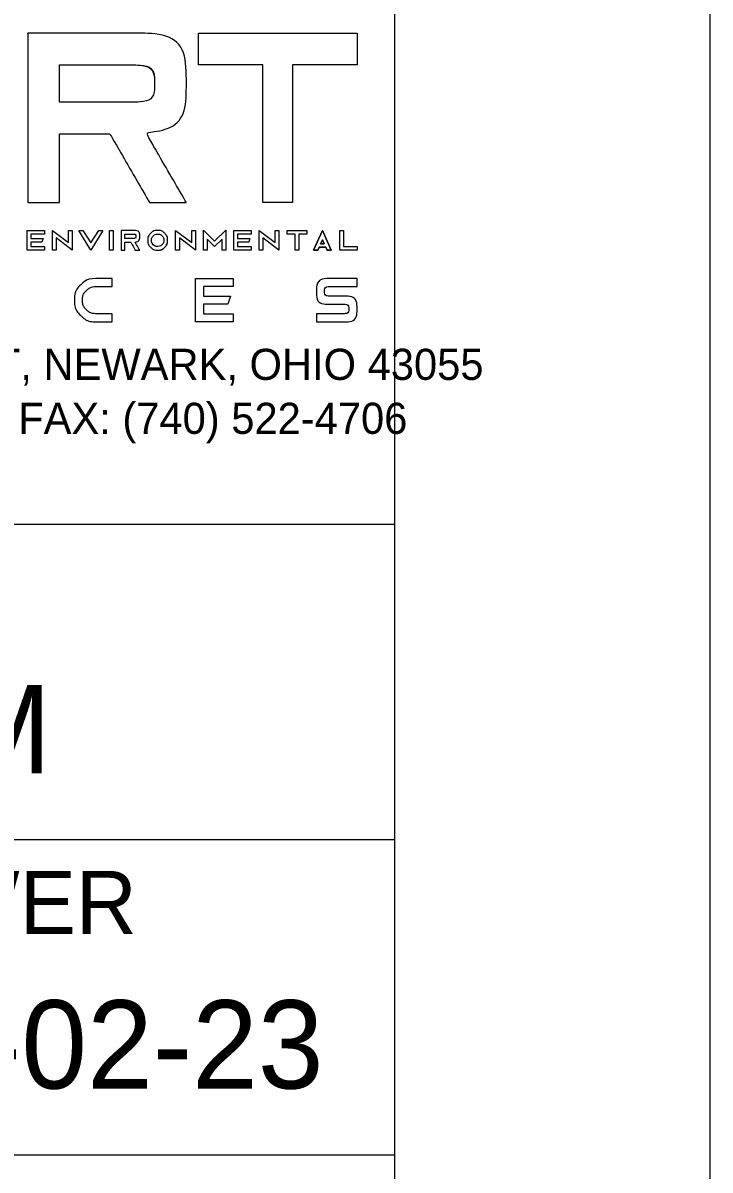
# Model space of a CAD drawing. Extents: x 0 to 34, y 0 to 22.
# Drawn here: x 32.911 to 34, y 1.976 to 3.795 of the extents above; entities that cross this region are included whole.
import ezdxf

# ---------------------------------------------------------------- set-up
doc = ezdxf.new("R2010")
doc.units = 0
for name, color, linetype in [('BORDER', 7, 'Continuous'), ('SH_Border', 7, 'Continuous'), ('SH_Cut_Line', 7, 'Continuous'), ('SH_Data', 7, 'Continuous')]:
    doc.layers.add(name, color=color, linetype=linetype)

msp = doc.modelspace()

# ---------------------------------------------------------------- linework, layer by layer
at = {"layer": 'BORDER'}
for p, q in [((33.1892, 3.7279), (33.1892, 3.7782)), ((33.1892, 3.7782), (33.4406, 3.7782)), ((33.4406, 3.7782), (33.4406, 3.7279)), ((33.2913, 3.7279), (33.1892, 3.7279)), ((33.2913, 3.51), (33.2913, 3.7279)), ((33.4406, 3.7279), (33.3384, 3.7279)), ((33.3384, 3.7279), (33.3384, 3.51)), ((33.3384, 3.51), (33.2913, 3.51)), ((32.9176, 3.4342), (32.9176, 3.4656)), ((32.9176, 3.4656), (32.9451, 3.4656)), ((32.9451, 3.4597), (32.9235, 3.4597)), ((32.9235, 3.4597), (32.9235, 3.4529)), ((32.9451, 3.4656), (32.9451, 3.4597)), ((32.9579, 3.4342), (32.9579, 3.4656)), ((32.9579, 3.4656), (32.9834, 3.4462)), ((32.9834, 3.4462), (32.9834, 3.4656)), ((32.9834, 3.4656), (32.9893, 3.4656)), ((32.9893, 3.4656), (32.9893, 3.4342)), ((33.0187, 3.4342), (32.9995, 3.4656)), ((32.9995, 3.4656), (33.0062, 3.4656)), ((33.0062, 3.4656), (33.0187, 3.446)), ((33.0187, 3.446), (33.0312, 3.4656)), ((33.0379, 3.4656), (33.0187, 3.4342)), ((33.0312, 3.4656), (33.0379, 3.4656)), ((33.0481, 3.4342), (33.0481, 3.4656)), ((33.0481, 3.4656), (33.054, 3.4656)), ((33.054, 3.4656), (33.054, 3.4342)), ((33.1531, 3.4342), (33.1531, 3.4656)), ((33.1531, 3.4656), (33.1786, 3.4462)), ((33.1786, 3.4462), (33.1786, 3.4656)), ((33.1786, 3.4656), (33.1845, 3.4656)), ((33.1845, 3.4656), (33.1845, 3.4342)), ((33.1973, 3.4342), (33.1973, 3.4661)), ((33.1973, 3.4661), (33.2149, 3.4484)), ((33.2149, 3.4484), (33.2326, 3.4661)), ((33.2326, 3.4661), (33.2326, 3.4342)), ((33.2453, 3.4342), (33.2453, 3.4656)), ((33.2453, 3.4656), (33.2728, 3.4656)), ((33.2728, 3.4597), (33.2512, 3.4597)), ((33.2512, 3.4597), (33.2512, 3.4529)), ((33.2728, 3.4656), (33.2728, 3.4597)), ((33.2856, 3.4342), (33.2856, 3.4656)), ((33.2856, 3.4656), (33.3111, 3.4462)), ((33.3111, 3.4462), (33.3111, 3.4656)), ((33.3111, 3.4656), (33.3169, 3.4656)), ((33.3169, 3.4656), (33.3169, 3.4342)), ((33.3297, 3.4597), (33.3297, 3.4656)), ((33.3297, 3.4656), (33.3611, 3.4656)), ((33.3425, 3.4597), (33.3297, 3.4597)), ((33.3425, 3.4342), (33.3425, 3.4597)), ((33.3611, 3.4597), (33.3483, 3.4597)), ((33.3483, 3.4597), (33.3483, 3.4342)), ((33.3611, 3.4656), (33.3611, 3.4597)), ((33.4131, 3.4656), (33.419, 3.4656)), ((33.4131, 3.4342), (33.4131, 3.4656)), ((33.419, 3.4656), (33.419, 3.4401)), ((32.9235, 3.4529), (32.9431, 3.4529)), ((32.9412, 3.447), (32.9235, 3.447)), ((32.9235, 3.447), (32.9235, 3.4401)), ((32.9235, 3.4401), (32.9451, 3.4401)), ((32.9431, 3.4529), (32.9412, 3.447)), ((32.9451, 3.4401), (32.9451, 3.4342)), ((32.9638, 3.4537), (32.9638, 3.4342)), ((32.9893, 3.4342), (32.9638, 3.4537)), ((33.159, 3.4537), (33.159, 3.4342)), ((33.1845, 3.4342), (33.159, 3.4537)), ((33.2031, 3.4519), (33.2031, 3.4342)), ((33.2149, 3.4401), (33.2031, 3.4519)), ((33.2267, 3.4519), (33.2149, 3.4401)), ((33.2267, 3.4342), (33.2267, 3.4519)), ((33.2512, 3.4529), (33.2708, 3.4529)), ((33.2689, 3.447), (33.2512, 3.447)), ((33.2512, 3.447), (33.2512, 3.4401)), ((33.2512, 3.4401), (33.2728, 3.4401)), ((33.2708, 3.4529), (33.2689, 3.447)), ((33.2728, 3.4401), (33.2728, 3.4342)), ((33.2914, 3.4537), (33.2914, 3.4342)), ((33.3169, 3.4342), (33.2914, 3.4537)), ((33.419, 3.4401), (33.4406, 3.4401)), ((33.4406, 3.4401), (33.4406, 3.4342)), ((32.9451, 3.4342), (32.9176, 3.4342)), ((32.9638, 3.4342), (32.9579, 3.4342)), ((33.054, 3.4342), (33.0481, 3.4342)), ((33.159, 3.4342), (33.1531, 3.4342)), ((33.2031, 3.4342), (33.1973, 3.4342)), ((33.2326, 3.4342), (33.2267, 3.4342)), ((33.2728, 3.4342), (33.2453, 3.4342)), ((33.2914, 3.4342), (33.2856, 3.4342)), ((33.3483, 3.4342), (33.3425, 3.4342)), ((33.4406, 3.4342), (33.4131, 3.4342)), ((33.1844, 3.3207), (33.1844, 3.3894)), ((33.1844, 3.3894), (33.2445, 3.3894)), ((33.2445, 3.3894), (33.2445, 3.3765)), ((33.2445, 3.3765), (33.1973, 3.3765)), ((33.1973, 3.3765), (33.1973, 3.3615)), ((33.1973, 3.3615), (33.2402, 3.3615)), ((33.2359, 3.3486), (33.1973, 3.3486)), ((33.1973, 3.3486), (33.1973, 3.3336)), ((33.2402, 3.3615), (33.2359, 3.3486)), ((33.1973, 3.3336), (33.2445, 3.3336)), ((33.2445, 3.3336), (33.2445, 3.3207)), ((33.2445, 3.3207), (33.1844, 3.3207))]:
    msp.add_line(p, q, dxfattribs=at)
for points in [[(33.2913, 3.7279), (33.1892, 3.7279), (33.1892, 3.7782), (33.4406, 3.7782), (33.4406, 3.7279), (33.3384, 3.7279), (33.3384, 3.51), (33.2913, 3.51), (33.2913, 3.7279)], [(32.9235, 3.4401), (32.9451, 3.4401), (32.9451, 3.4342), (32.9176, 3.4342), (32.9176, 3.4656), (32.9451, 3.4656), (32.9451, 3.4597), (32.9235, 3.4597), (32.9235, 3.4529), (32.9431, 3.4529), (32.9412, 3.447), (32.9235, 3.447), (32.9235, 3.4401)], [(32.9638, 3.4537), (32.9638, 3.4342), (32.9579, 3.4342), (32.9579, 3.4656), (32.9834, 3.4462), (32.9834, 3.4656), (32.9893, 3.4656), (32.9893, 3.4342), (32.9638, 3.4537)], [(33.0062, 3.4656), (33.0187, 3.446), (33.0312, 3.4656), (33.0379, 3.4656), (33.0187, 3.4342), (32.9995, 3.4656), (33.0062, 3.4656)], [(33.054, 3.4342), (33.0481, 3.4342), (33.0481, 3.4656), (33.054, 3.4656), (33.054, 3.4342)], [(33.159, 3.4537), (33.159, 3.4342), (33.1531, 3.4342), (33.1531, 3.4656), (33.1786, 3.4462), (33.1786, 3.4656), (33.1845, 3.4656), (33.1845, 3.4342), (33.159, 3.4537)], [(33.2031, 3.4519), (33.2031, 3.4342), (33.1973, 3.4342), (33.1973, 3.4661), (33.2149, 3.4484), (33.2326, 3.4661), (33.2326, 3.4342), (33.2267, 3.4342), (33.2267, 3.4519), (33.2149, 3.4401), (33.2031, 3.4519)], [(33.2512, 3.4401), (33.2728, 3.4401), (33.2728, 3.4342), (33.2453, 3.4342), (33.2453, 3.4656), (33.2728, 3.4656), (33.2728, 3.4597), (33.2512, 3.4597), (33.2512, 3.4529), (33.2708, 3.4529), (33.2689, 3.447), (33.2512, 3.447), (33.2512, 3.4401)], [(33.2914, 3.4537), (33.2914, 3.4342), (33.2856, 3.4342), (33.2856, 3.4656), (33.3111, 3.4462), (33.3111, 3.4656), (33.3169, 3.4656), (33.3169, 3.4342), (33.2914, 3.4537)], [(33.3425, 3.4597), (33.3297, 3.4597), (33.3297, 3.4656), (33.3611, 3.4656), (33.3611, 3.4597), (33.3483, 3.4597), (33.3483, 3.4342), (33.3425, 3.4342), (33.3425, 3.4597)], [(33.3856, 3.4656), (33.3997, 3.4342), (33.393, 3.4342), (33.3909, 3.4389), (33.3804, 3.4389), (33.3783, 3.4342), (33.3716, 3.4342), (33.3856, 3.4656)], [(33.4131, 3.4656), (33.419, 3.4656), (33.419, 3.4401), (33.4406, 3.4401), (33.4406, 3.4342), (33.4131, 3.4342), (33.4131, 3.4656)], [(33.3884, 3.4444), (33.3856, 3.4509), (33.3828, 3.4444), (33.3884, 3.4444)], [(33.1973, 3.3336), (33.2445, 3.3336), (33.2445, 3.3207), (33.1844, 3.3207), (33.1844, 3.3894), (33.2445, 3.3894), (33.2445, 3.3765), (33.1973, 3.3765), (33.1973, 3.3615), (33.2402, 3.3615), (33.2359, 3.3486), (33.1973, 3.3486), (33.1973, 3.3336)]]:
    msp.add_lwpolyline(points, dxfattribs=at)
for points in [[(33.3716, 3.4342), (33.3783, 3.4342), (33.3804, 3.4389), (33.3909, 3.4389), (33.393, 3.4342), (33.3997, 3.4342), (33.3856, 3.4656)], [(33.3828, 3.4444), (33.3856, 3.4509), (33.3884, 3.4444)]]:
    msp.add_lwpolyline(points, close=True, dxfattribs=at)
for points, degree in [([(32.9187, 3.7782), (32.9187, 3.7782), (32.9187, 3.51), (32.9187, 3.51)], 2), ([(32.9187, 3.51), (32.9187, 3.51), (32.969, 3.51), (32.969, 3.51), (32.969, 3.51), (32.969, 3.6189), (32.969, 3.6189), (32.969, 3.6189), (33.0488, 3.6189), (33.0488, 3.6189), (33.0488, 3.6189), (33.1116, 3.51), (33.1116, 3.51), (33.1116, 3.51), (33.1698, 3.51), (33.1698, 3.51), (33.1698, 3.51), (33.1061, 3.6203), (33.1061, 3.6203), (33.1488, 3.6261), (33.1701, 3.6522), (33.1701, 3.6986), (33.1701, 3.7516), (33.1422, 3.7782), (33.0863, 3.7782), (33.0863, 3.7782), (32.9187, 3.7782), (32.9187, 3.7782)], 3), ([(32.9187, 3.7782), (32.9187, 3.7782), (33.0863, 3.7782), (33.0863, 3.7782), (33.1422, 3.7782), (33.1701, 3.7516), (33.1701, 3.6986), (33.1701, 3.6522), (33.1488, 3.6261), (33.1061, 3.6203), (33.1061, 3.6203), (33.1698, 3.51), (33.1698, 3.51), (33.1698, 3.51), (33.1116, 3.51), (33.1116, 3.51), (33.1116, 3.51), (33.0488, 3.6189), (33.0488, 3.6189), (33.0488, 3.6189), (32.969, 3.6189), (32.969, 3.6189), (32.969, 3.6189), (32.969, 3.51), (32.969, 3.51), (32.969, 3.51), (32.9187, 3.51), (32.9187, 3.51), (32.9187, 3.51), (32.9187, 3.7782), (32.9187, 3.7782)], 3), ([(32.969, 3.7279), (32.969, 3.7279), (33.0863, 3.7279), (33.0863, 3.7279)], 2), ([(33.0863, 3.7279), (33.1086, 3.7279), (33.1198, 3.7181), (33.1198, 3.6986), (33.1198, 3.679), (33.1086, 3.6692), (33.0863, 3.6692), (33.0863, 3.6692), (32.969, 3.6692), (32.969, 3.6692), (32.969, 3.6692), (32.969, 3.7279), (32.969, 3.7279)], 3), ([(32.969, 3.7279), (32.969, 3.7279), (32.969, 3.6692), (32.969, 3.6692), (32.969, 3.6692), (33.0863, 3.6692), (33.0863, 3.6692), (33.1086, 3.6692), (33.1198, 3.679), (33.1198, 3.6986), (33.1198, 3.7181), (33.1086, 3.7279), (33.0863, 3.7279), (33.0863, 3.7279), (32.969, 3.7279), (32.969, 3.7279)], 3), ([(33.0668, 3.4656), (33.0668, 3.4656), (33.0668, 3.4342), (33.0668, 3.4342)], 2), ([(33.0668, 3.4656), (33.0668, 3.4656), (33.0864, 3.4656), (33.0864, 3.4656), (33.0929, 3.4656), (33.0962, 3.4625), (33.0962, 3.4563), (33.0962, 3.4509), (33.0937, 3.4478), (33.0887, 3.4471), (33.0887, 3.4471), (33.0962, 3.4342), (33.0962, 3.4342), (33.0962, 3.4342), (33.0894, 3.4342), (33.0894, 3.4342), (33.0894, 3.4342), (33.082, 3.447), (33.082, 3.447), (33.082, 3.447), (33.0727, 3.447), (33.0727, 3.447), (33.0727, 3.447), (33.0727, 3.4342), (33.0727, 3.4342), (33.0727, 3.4342), (33.0668, 3.4342), (33.0668, 3.4342), (33.0668, 3.4342), (33.0668, 3.4656), (33.0668, 3.4656)], 3), ([(33.0668, 3.4342), (33.0668, 3.4342), (33.0727, 3.4342), (33.0727, 3.4342), (33.0727, 3.4342), (33.0727, 3.447), (33.0727, 3.447), (33.0727, 3.447), (33.082, 3.447), (33.082, 3.447), (33.082, 3.447), (33.0894, 3.4342), (33.0894, 3.4342), (33.0894, 3.4342), (33.0962, 3.4342), (33.0962, 3.4342), (33.0962, 3.4342), (33.0887, 3.4471), (33.0887, 3.4471), (33.0937, 3.4478), (33.0962, 3.4509), (33.0962, 3.4563), (33.0962, 3.4625), (33.0929, 3.4656), (33.0864, 3.4656), (33.0864, 3.4656), (33.0668, 3.4656), (33.0668, 3.4656)], 3), ([(33.0727, 3.4597), (33.0727, 3.4597), (33.0864, 3.4597), (33.0864, 3.4597)], 2), ([(33.0727, 3.4597), (33.0727, 3.4597), (33.0727, 3.4529), (33.0727, 3.4529), (33.0727, 3.4529), (33.0864, 3.4529), (33.0864, 3.4529), (33.089, 3.4529), (33.0903, 3.454), (33.0903, 3.4563), (33.0903, 3.4586), (33.089, 3.4597), (33.0864, 3.4597), (33.0864, 3.4597), (33.0727, 3.4597), (33.0727, 3.4597)], 3), ([(33.0864, 3.4597), (33.089, 3.4597), (33.0903, 3.4586), (33.0903, 3.4563), (33.0903, 3.454), (33.089, 3.4529), (33.0864, 3.4529), (33.0864, 3.4529), (33.0727, 3.4529), (33.0727, 3.4529), (33.0727, 3.4529), (33.0727, 3.4597), (33.0727, 3.4597)], 3), ([(33.1247, 3.4342), (33.1203, 3.4342), (33.1166, 3.4358), (33.1136, 3.4388), (33.1105, 3.4419), (33.109, 3.4456), (33.109, 3.4499), (33.109, 3.4543), (33.1105, 3.4579), (33.1136, 3.461), (33.1166, 3.4641), (33.1203, 3.4656), (33.1247, 3.4656), (33.129, 3.4656), (33.1327, 3.4641), (33.1358, 3.461), (33.1388, 3.4579), (33.1404, 3.4543), (33.1404, 3.4499), (33.1404, 3.4456), (33.1388, 3.4419), (33.1358, 3.4388), (33.1327, 3.4358), (33.129, 3.4342), (33.1247, 3.4342)], 3), ([(33.1358, 3.4388), (33.1388, 3.4419), (33.1404, 3.4456), (33.1404, 3.4499), (33.1404, 3.4543), (33.1388, 3.4579), (33.1358, 3.461), (33.1327, 3.4641), (33.129, 3.4656), (33.1247, 3.4656), (33.1203, 3.4656), (33.1166, 3.4641), (33.1136, 3.461), (33.1105, 3.4579), (33.109, 3.4543), (33.109, 3.4499), (33.109, 3.4456), (33.1105, 3.4419), (33.1136, 3.4388), (33.1166, 3.4358), (33.1203, 3.4342), (33.1247, 3.4342)], 3), ([(33.1247, 3.4401), (33.1274, 3.4401), (33.1297, 3.4411), (33.1316, 3.443), (33.1335, 3.4449), (33.1345, 3.4472), (33.1345, 3.4499), (33.1345, 3.4526), (33.1335, 3.4549), (33.1316, 3.4569), (33.1297, 3.4588), (33.1274, 3.4597), (33.1247, 3.4597), (33.122, 3.4597), (33.1196, 3.4588), (33.1177, 3.4569), (33.1158, 3.4549), (33.1149, 3.4526), (33.1149, 3.4499), (33.1149, 3.4472), (33.1158, 3.4449), (33.1177, 3.443), (33.1196, 3.4411), (33.122, 3.4401), (33.1247, 3.4401)], 3), ([(33.1177, 3.443), (33.1158, 3.4449), (33.1149, 3.4472), (33.1149, 3.4499), (33.1149, 3.4526), (33.1158, 3.4549), (33.1177, 3.4569), (33.1196, 3.4588), (33.122, 3.4597), (33.1247, 3.4597), (33.1274, 3.4597), (33.1297, 3.4588), (33.1316, 3.4569), (33.1335, 3.4549), (33.1345, 3.4526), (33.1345, 3.4499), (33.1345, 3.4472), (33.1335, 3.4449), (33.1316, 3.443), (33.1297, 3.4411), (33.1274, 3.4401), (33.1247, 3.4401)], 3), ([(33.1247, 3.4401), (33.122, 3.4401), (33.1196, 3.4411), (33.1177, 3.443)], 2), ([(33.1247, 3.4342), (33.129, 3.4342), (33.1327, 3.4358), (33.1358, 3.4388)], 2), ([(33.0269, 3.3894), (33.0269, 3.3894), (33.0527, 3.3894), (33.0527, 3.3894), (33.0527, 3.3894), (33.0527, 3.3765), (33.0527, 3.3765), (33.0527, 3.3765), (33.0269, 3.3765), (33.0269, 3.3765), (33.021, 3.3765), (33.0159, 3.3744), (33.0118, 3.3702), (33.0076, 3.366), (33.0055, 3.361), (33.0055, 3.3551), (33.0055, 3.3491), (33.0076, 3.3441), (33.0118, 3.3399), (33.0159, 3.3357), (33.021, 3.3336), (33.0269, 3.3336), (33.0269, 3.3336), (33.0527, 3.3336), (33.0527, 3.3336), (33.0527, 3.3336), (33.0527, 3.3207), (33.0527, 3.3207), (33.0527, 3.3207), (33.0269, 3.3207), (33.0269, 3.3207), (33.0175, 3.3207), (33.0094, 3.3241), (33.0027, 3.3308), (32.9959, 3.3375), (32.9926, 3.3456), (32.9926, 3.3551), (32.9926, 3.3645), (32.9959, 3.3726), (33.0027, 3.3793), (33.0094, 3.3861), (33.0175, 3.3894), (33.0269, 3.3894)], 3), ([(33.0269, 3.3894), (33.0269, 3.3894), (33.0527, 3.3894), (33.0527, 3.3894), (33.0527, 3.3894), (33.0527, 3.3765), (33.0527, 3.3765), (33.0527, 3.3765), (33.0269, 3.3765), (33.0269, 3.3765), (33.021, 3.3765), (33.0159, 3.3744), (33.0118, 3.3702), (33.0076, 3.366), (33.0055, 3.361), (33.0055, 3.3551), (33.0055, 3.3491), (33.0076, 3.3441), (33.0118, 3.3399), (33.0159, 3.3357), (33.021, 3.3336), (33.0269, 3.3336), (33.0269, 3.3336), (33.0527, 3.3336), (33.0527, 3.3336), (33.0527, 3.3336), (33.0527, 3.3207), (33.0527, 3.3207), (33.0527, 3.3207), (33.0269, 3.3207), (33.0269, 3.3207), (33.0175, 3.3207), (33.0094, 3.3241), (33.0027, 3.3308), (32.9959, 3.3375), (32.9926, 3.3456), (32.9926, 3.3551), (32.9926, 3.3645), (32.9959, 3.3726), (33.0027, 3.3793), (33.0094, 3.3861), (33.0175, 3.3894), (33.0269, 3.3894)], 3), ([(33.3976, 3.3894), (33.3976, 3.3894), (33.4406, 3.3894), (33.4406, 3.3894), (33.4406, 3.3894), (33.4406, 3.3765), (33.4406, 3.3765), (33.4406, 3.3765), (33.3976, 3.3765), (33.3976, 3.3765), (33.3919, 3.3765), (33.389, 3.374), (33.389, 3.369), (33.389, 3.364), (33.3919, 3.3615), (33.3976, 3.3615), (33.3976, 3.3615), (33.4191, 3.3615), (33.4191, 3.3615), (33.4334, 3.3615), (33.4406, 3.3547), (33.4406, 3.3411), (33.4406, 3.3275), (33.4334, 3.3207), (33.4191, 3.3207), (33.4191, 3.3207), (33.3762, 3.3207), (33.3762, 3.3207), (33.3762, 3.3207), (33.3762, 3.3336), (33.3762, 3.3336), (33.3762, 3.3336), (33.4191, 3.3336), (33.4191, 3.3336), (33.4248, 3.3336), (33.4277, 3.3361), (33.4277, 3.3411), (33.4277, 3.3461), (33.4248, 3.3486), (33.4191, 3.3486), (33.4191, 3.3486), (33.3976, 3.3486), (33.3976, 3.3486), (33.3833, 3.3486), (33.3762, 3.3554), (33.3762, 3.369), (33.3762, 3.3826), (33.3833, 3.3894), (33.3976, 3.3894)], 3), ([(33.3976, 3.3894), (33.3976, 3.3894), (33.4406, 3.3894), (33.4406, 3.3894), (33.4406, 3.3894), (33.4406, 3.3765), (33.4406, 3.3765), (33.4406, 3.3765), (33.3976, 3.3765), (33.3976, 3.3765), (33.3919, 3.3765), (33.389, 3.374), (33.389, 3.369), (33.389, 3.364), (33.3919, 3.3615), (33.3976, 3.3615), (33.3976, 3.3615), (33.4191, 3.3615), (33.4191, 3.3615), (33.4334, 3.3615), (33.4406, 3.3547), (33.4406, 3.3411), (33.4406, 3.3275), (33.4334, 3.3207), (33.4191, 3.3207), (33.4191, 3.3207), (33.3762, 3.3207), (33.3762, 3.3207), (33.3762, 3.3207), (33.3762, 3.3336), (33.3762, 3.3336), (33.3762, 3.3336), (33.4191, 3.3336), (33.4191, 3.3336), (33.4248, 3.3336), (33.4277, 3.3361), (33.4277, 3.3411), (33.4277, 3.3461), (33.4248, 3.3486), (33.4191, 3.3486), (33.4191, 3.3486), (33.3976, 3.3486), (33.3976, 3.3486), (33.3833, 3.3486), (33.3762, 3.3554), (33.3762, 3.369), (33.3762, 3.3826), (33.3833, 3.3894), (33.3976, 3.3894)], 3)]:
    msp.add_open_spline(points, degree=degree, dxfattribs=at)
at = {"layer": 'SH_Border'}
for p, q in [((32, 3), (33.5, 3)), ((32, 2.5), (33.5, 2.5)), ((32, 2), (33.5, 2))]:
    msp.add_line(p, q, dxfattribs=at)
msp.add_lwpolyline([(1.5, 21.5), (33.5, 21.5), (33.5, 0.5), (1.5, 0.5)], close=True, dxfattribs=at)
at = {"layer": 'SH_Cut_Line'}
msp.add_lwpolyline([(0, 0), (34, 0), (34, 22), (0, 22)], close=True, dxfattribs=at)

# ---------------------------------------------------------------- texts
at = {"layer": 'BORDER'}
for s, p in [('88 W. CHURCH STREET, NEWARK, OHIO 43055', (32.1511, 3.2286)), ('PHONE: (740) 345-4700   FAX: (740) 522-4706', (32.1254, 3.143))]:
    msp.add_text(s, height=0.049387, dxfattribs=at).set_placement(p)
at = {"layer": 'SH_Data'}
for s, height, p in [('NAM', 0.14, (32.54, 2.605)), ('REVIEWER', 0.1, (32.3783, 2.35)), ('03-02-23', 0.14, (32.6381, 2.105))]:
    msp.add_text(s, height=height, dxfattribs=at).set_placement(p)

doc.saveas('drawing.dxf')
